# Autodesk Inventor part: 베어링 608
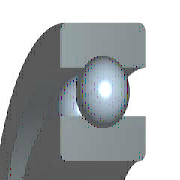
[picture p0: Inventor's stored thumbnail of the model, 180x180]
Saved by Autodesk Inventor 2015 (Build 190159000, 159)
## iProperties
IsCustomPart: 1
Created: 2012-02
Part Number: 베어링 608
Material: 강철, 연강
Description: 깊은 그루브 볼 베어링
Document SubType Name: Modeling
Standard: KS B 2023
Designer: mduedu
Standards Organization: KS
Language: ko-KR
Size Designation: 608 - 8 x 22 x 7
Categories: <MemberInstance><Categories><Category DisplayName="샤프트 부품" InternalName="7f7aeb1f-a693-4053-b835-cee3144e0d98" Mnemonic="SHFT"><Category DisplayName="베어링" Inter
Density: 7.85 g/cm^3
Appearance: 주황색
Mass: 12.145 g
Surface Area: 20.0754 cm^2
Volume: 1.54714 cm^3
Author: mduedu
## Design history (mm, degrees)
sketch "스케치" dims "d0" = 3.64 (= -0.26 x WD + 0.26 x BD)
  geometry: L1 (1.68, 7.5)-(5.32, 7.5); L2 (3.5, 7.5)-(3.5, 5.68); L3 (3.5, 7.5)-(3.5, 9.32); L4 (2.148, 6.282)-(0, 6.282); L5 (0, 4)-(7, 4); L6 (2.148, 8.718)-(0, 8.718); L7 (0, 11)-(7, 11); L8 (7, 4)-(7, 6.282); L9 (4.852, 6.282)-(7, 6.282); L10 (4.852, 8.718)-(7, 8.718); L11 (7, 11)-(7, 8.718); L12 (-1.4, 0)-(8.4, 0) reference; L13 (0, -0.3)-(0, 5.3) reference
  constraints: 22 end point, 4 point on line, 2 collinear, 2 perpendicular, 2 symmetric about line, 1 midpoint, 1 parallel, 14 other
  dimensions: "d9" = 8 diameter of L5 L12 (= WD); "d11" = 22 diameter of L7 L12 (= BD); "d12" = 7 distance between parallel lines of L8 L13 (= KB); "d13" = 12.564 diameter of L9 L12 (= 0.326 x BD + 0.674 x WD)
revolve "본체" stored, may be unused: angle "d6" = 90 deg
revolve "볼" stored, may be unused: angle "d7" = 90 deg
pattern_circular "IDS_ARRAYBALL[SIMPL:T]" dims angle "d3" = 360 deg
body "Solid1"
fillet "모깎기1" dims "d1" = 0.3 (= KRS)
other parameters: "WD" = 8 [user parameter; used in 5 equation terms], "BD" = 22 [user parameter; used in 5 equation terms], "KB" = 7 [user parameter; used in 1 equation term], "KRS" = 0.3 [user parameter; used in 1 equation term], "d4" = 0, "d5" = 0, "d8" = 0, "d14" = 0, "d15" = 0, "BBA" = 0 [user parameter], "BC0" = 1370000 [user parameter], "BC" = 3250000 [user parameter], "BR" = 11 (= 0.5 x BD) [user parameter], "WR" = 4 (= 0.5 x WD) [user parameter]
